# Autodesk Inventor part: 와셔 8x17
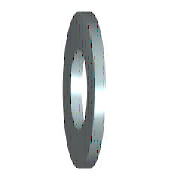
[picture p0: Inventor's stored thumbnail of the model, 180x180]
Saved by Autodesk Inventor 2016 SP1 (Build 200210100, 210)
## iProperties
IsCustomPart: 1
Created: 2012-02
Part Number: 와셔 8x17
Material: 강철, 연강
Description: 평면 와셔
Document SubType Name: Modeling
Standard: KS B 1326
Designer: mduedu
Standards Organization: KS
Language: ko-KR
Size Designation: 8x17
Categories: <MemberInstance><Categories><Category DisplayName="조임쇠" InternalName="e4da775c-781d-43d5-af7c-5136215cf5a6" Mnemonic="FSTN"><Category DisplayName="와셔" InternalN
Density: 1 g/cm^3
Appearance: 주황색
Author: mduedu
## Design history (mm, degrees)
sketch "스케치"
  geometry: C1 r 8.5 at (0, 0); C2 r 4.2 at (0, 0); 1 further point
  constraints: 2 centre point, 2 coincident
  dimensions: "d0" = 8.4 diameter of C2 (= SD1); "d1" = 17 diameter of C1 (= SD2)
extrude "본체" new body sketch "스케치" distance "d2" = 1.6 (= SD); taper "d3" = 0 deg
workaxis "Work Axis1"
workplane "Work Plane1"
body "Solid1"
other parameters: "SD1" = 8.4 [user parameter; used in 1 equation term], "SD2" = 17 [user parameter; used in 1 equation term], "SD" = 1.6 [user parameter; used in 1 equation term], "d4" = 0, "d5" = 0, "d6" = 0, "d7" = 0, "NND" = 8 [user parameter]
